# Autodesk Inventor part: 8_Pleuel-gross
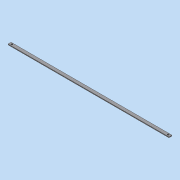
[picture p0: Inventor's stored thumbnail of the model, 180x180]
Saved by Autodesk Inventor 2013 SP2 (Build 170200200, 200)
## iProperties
Created: 2014-01
Part Number: 8_Pleuel-gross
Material: Allgemein
Document SubType Name: Modeling
Designer: J. Palme
Density: 1 g/cm^3
Author: J. Palme
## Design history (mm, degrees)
sketch "Skizze1"
  geometry: L1 (-1.45, 0.902)-(101.552, 0.902); L2 (101.552, 0.902)-(101.552, -1.031); L3 (101.552, -1.031)-(-1.45, -1.031); L4 (-1.45, -1.031)-(-1.45, 0.902); C1 r 0.5 at (0, 0); C2 r 0.5 at (100, 0); 1 further point
  constraints: 8 end point, 2 centre point, 2 parallel, 1 coincident, 1 equal radius, 1 horizontal, 1 perpendicular
  dimensions: "d0" = 100 distance of C2.centre C1.centre; "d2" = 1 diameter of C1
extrude "Extrusion1" new body sketch "Skizze1" distance "d3" = 0.5; taper "d4" = 0 deg
node "Volumenkörper1"
